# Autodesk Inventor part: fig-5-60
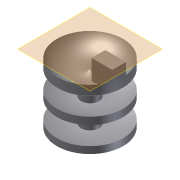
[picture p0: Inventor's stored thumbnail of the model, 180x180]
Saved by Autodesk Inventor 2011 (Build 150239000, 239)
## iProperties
Created: 2004-05
Part Number: fig-5-60
Document SubType Name: Modeling
Designer: CADCIM Technologies
Manufacturer: Standard
Standards Organization: Custom
Density: 1 g/cm^3
Author: CADCIM Technologies
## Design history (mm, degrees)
sketch "Sketch1"
  geometry: L1 (0.098, 22.743)-(0.098, 0.516); L2 (-3.621, 19.305)-(-3.621, 13.061); L3 (-3.621, 10.379)-(-3.621, 3.25); L4 (-3.664, 0.516)-(0.098, 0.516); L5 (-13.694, 4.7)-(-13.694, 1.836); L6 (-13.694, 26.851)-(-13.694, 23.014); L7 (-13.694, 15.335)-(-13.694, 12.343); A1 r 10.546 centre (-4.597, 32.185) between (-13.694, 26.851) and (0.098, 22.743); A2 r 21.828 centre (-4.597, 32.185) between (-13.694, 12.343) and (-3.621, 10.379); A3 r 12.918 centre (-4.597, 32.185) between (-13.694, 23.014) and (-3.621, 19.305); A4 r 19.149 centre (-4.597, 32.185) between (-13.694, 15.335) and (-3.621, 13.061); A5 r 28.952 centre (-4.597, 32.185) between (-13.694, 4.7) and (-3.621, 3.25); A6 r 31.683 centre (-4.597, 32.185) between (-13.694, 1.836) and (-3.664, 0.516)
  constraints: 14 end point, 12 point on circle, 6 centre point, 4 perpendicular, 2 parallel, 1 vertical
revolve "Revolution1" sketch "Sketch1" stored, may be unused: angle "d0" = 90 deg
workplane "Work Plane1"
sketch "Sketch2"
  geometry: L1 (3.408, -2.846)-(12.06, -2.846); L2 (12.06, -2.846)-(12.06, 2.873); L3 (12.06, 2.873)-(3.408, 2.873); L4 (3.408, 2.873)-(3.408, -2.846)
  constraints: 8 end point, 2 parallel, 1 horizontal, 1 perpendicular
extrude "Extrusion3" join sketch "Sketch2" stored distance "d8" = 10; taper "d9" = 0 deg
body "Solid1"
